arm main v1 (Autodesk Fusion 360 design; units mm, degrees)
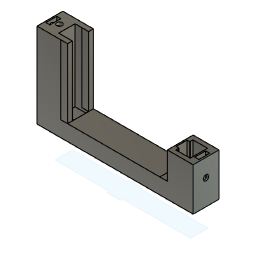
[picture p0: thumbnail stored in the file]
sketch "草图1" plane through (0, 0, 0) normal (0, 0, 1) x axis (1, 0, 0)
  line L1 (57.5, 9.5) -> (-57.5, 9.5)
  line L2 (57.5, -9.5) -> (57.5, 9.5)
  line L3 (-57.5, -9.5) -> (57.5, -9.5)
  line L4 (-57.5, 9.5) -> (-57.5, -9.5)
  line L5 (57.5, -9.5) -> (-57.5, 9.5)
  line L6 (-57.5, -9.5) -> (57.5, 9.5)
  point P6 (0, 0)
  point P1 (0, 0)
  point P4 (57.5, -9.5)
  point P5 (-57.5, -9.5)
  horizontal L1
  perpendicular L1 L2
  parallel L1 L3
  parallel L2 L4
  coincident L5 P6
  coincident L6 P6
  coincident P1 P6
  dimension "d1" distance P4 P5 = 115
  dimension "d2" distance L1 L3 = 19
extrude "拉伸1" new body sketch "草图1" profile of L1 L2 L3 L4 along normal blind 10
sketch "草图2" plane through (0, 0, 10) normal (0, 0, 1) x axis (-1, 0, 0)
  line L1 (-57.5, 9.5) -> (57.5, 9.5)
  line L2 (-57.5, -9.5) -> (-57.5, 9.5)
  line L3 (57.5, -9.5) -> (-57.5, -9.5)
  line L4 (57.5, 9.5) -> (57.5, -9.5)
  line L5 (-38.5, 9.5) -> (-57.5, 9.5)
  line L6 (-38.5, -9.5) -> (-38.5, 9.5)
  line L7 (-57.5, -9.5) -> (-38.5, -9.5)
  line L8 (-57.5, 9.5) -> (-57.5, -9.5)
  point P3 (-57.5, 9.5)
  point P6 (-57.5, 9.5)
  point P7 (-38.5, 9.5)
  horizontal L5
  vertical L6
  horizontal L7
  vertical L8
  coincident P3 P6
  dimension "d5" distance P6 P7 = 19
extrude "拉伸2" add sketch "草图2" profile of L1 L2 L3 L5 L6 L7 L8 along normal blind 20
sketch "草图3" plane through (0, 0, 30) normal (0, 0, 1) x axis (-1, 0, 0)
  line L1 (-38.5, -9.5) -> (-57.5, -9.5)
  line L2 (-38.5, 9.5) -> (-38.5, -9.5)
  line L3 (-57.5, 9.5) -> (-38.5, 9.5)
  line L4 (-57.5, -9.5) -> (-57.5, 9.5)
  line L5 (-41.5, 6.353) -> (-52.2, 6.353)
  line L6 (-52.2, -6.347) -> (-41.5, -6.347)
  line L7 (-41.5, -6.347) -> (-52.2, 6.353)
  line L8 (-52.2, -6.347) -> (-41.5, 6.353)
  line L9 (-52.2, -5.5) -> (-52.2, -6.347)
  line L10 (-52.2, 6.353) -> (-52.2, 5.5)
  line L11 (-52.2, -5.5) -> (-52.2, 5.5)
  line L12 (-41.5, 4.5005) -> (-41.5, 6.353)
  line L13 (-41.5, -6.347) -> (-41.5, -4.4995)
  line L14 (-39.5, 3.9901) -> (-41.5, 3.9901)
  line L15 (-39.5, -4.0099) -> (-39.5, 3.9901)
  line L16 (-41.5, -4.0099) -> (-39.5, -4.0099)
  line L17 (-39.5, -4.0099) -> (-41.5, 3.9901)
  line L18 (-41.5, -4.0099) -> (-39.5, 3.9901)
  line L19 (-56.2, 4) -> (-53.2, 4)
  line L20 (-56.2, -4) -> (-56.2, 4)
  line L21 (-53.2, -4) -> (-56.2, -4)
  line L22 (-53.2, 4) -> (-53.2, -4)
  line L23 (-56.2, -4) -> (-53.2, 4)
  line L24 (-53.2, -4) -> (-56.2, 4)
  line L25 (-41.5, 3.9901) -> (-41.5, 4.5005)
  line L26 (-41.5, -4.4995) -> (-41.5, -4.0099)
  point P10 (-46.85, 0.003)
  point P11 (-52.2, 5.5)
  point P20 (-40.5, -0.0099)
  point P15 (-40.5, -0.0099)
  point P25 (-54.7, 0)
  point P26 (-41.5, 3.9901)
  point P18 (-39.5, -4.0099)
  point P19 (-41.5, -4.0099)
  horizontal L5
  perpendicular L5 L12
  parallel L5 L6
  parallel L9 L12
  coincident L7 P10
  coincident L8 P10
  coincident P11 L9
  collinear L9 L10
  collinear L12 L13
  parallel L13 L25
  horizontal L14
  perpendicular L14 L15
  parallel L14 L16
  coincident L17 P20
  coincident L18 P20
  coincident P15 P20
  horizontal L19
  perpendicular L19 L20
  parallel L19 L21
  parallel L20 L22
  coincident L23 P25
  coincident L24 P25
  collinear L25 L26
  coincident L17 P26
  dimension "d24" distance L9 L12 = 10.7
  dimension "d25" distance L5 L6 = 12.7
  dimension "d26" distance L2 L12 = 3
  dimension "d32" distance P18 P19 = 2
  dimension "d33" distance L14 L16 = 8
  dimension "d34" distance P15 L25 = 1
  dimension "d35" distance L19 L21 = 8
  dimension "d36" distance L20 L22 = 3
  dimension "d37" distance L11 L22 = 1
sketch "草图4" plane through (38.5, 0, 0) normal (-1, 0, 0) x axis (0, -1, 0)
  line L1 (9.5, 10) -> (-9.5, 10)
  line L2 (9.5, 30) -> (9.5, 10)
  line L3 (-9.5, 30) -> (9.5, 30)
  line L4 (-9.5, 10) -> (-9.5, 30)
  circle C1 centre (0, 17) radius 2
  point P6 (0, 17)
  dimension "d20" diameter C1 = 4
  dimension "d21" distance L3 P6 = 13
extrude "拉伸6" cut sketch "草图3" profile of L5 L13 L6 L10 L11 L26 L14 L15 L16 against normal blind 47
extrude "拉伸7" cut sketch "草图3" profile of L19 L20 L21 L22 against normal blind 17
sketch "草图5" plane through (57.5, 0, 0) normal (1, 0, 0) x axis (0, 1, 0)
  line L1 (9.5, 0) -> (-9.5, 0)
  line L2 (9.5, 30) -> (9.5, 0)
  line L3 (-9.5, 30) -> (9.5, 30)
  line L4 (-9.5, 0) -> (-9.5, 30)
  circle C1 centre (0, 22) radius 2
  point P6 (0, 22)
  dimension "d42" diameter C1 = 4
  dimension "d43" distance L3 P6 = 8
extrude "拉伸8" cut sketch "草图5" profile of C1 against normal blind 13
sketch "草图6" plane through (0, 0, 10) normal (0, 0, 1) x axis (-1, 0, 0)
  line L1 (-38.5, -9.5) -> (-38.5, 9.5)
  line L2 (57.5, -9.5) -> (-38.5, -9.5)
  line L3 (57.5, 9.5) -> (57.5, -9.5)
  line L4 (-38.5, 9.5) -> (57.5, 9.5)
  line L5 (56.5, -4) -> (53.5, -4)
  line L6 (56.5, 4) -> (56.5, -4)
  line L7 (53.5, 4) -> (56.5, 4)
  line L8 (53.5, -4) -> (53.5, 4)
  line L9 (56.5, 4) -> (53.5, -4)
  line L10 (53.5, 4) -> (56.5, -4)
  circle C1 centre (50.5, 0) radius 2
  point P10 (55, 0)
  point P8 (56.5, 4)
  point P9 (53.5, 4)
  point P11 (50.5, 0)
  horizontal L5
  perpendicular L5 L6
  parallel L5 L7
  parallel L6 L8
  coincident L9 P10
  coincident L10 P10
  dimension "d48" distance P8 P9 = 3
  dimension "d49" distance L5 L7 = 8
  dimension "d131" diameter C1 = 4
  dimension "d132" distance L8 P11 = 3
extrude "拉伸10" cut sketch "草图6" profile of L5 L6 L7 L8 against normal blind 8
sketch "草图7" plane through (-57.5, 0, 0) normal (-1, 0, 0) x axis (0, -1, 0)
  line L1 (9.5, 0) -> (-9.5, 0)
  line L2 (9.5, 10) -> (9.5, 0)
  line L3 (-9.5, 10) -> (9.5, 10)
  line L4 (-9.5, 0) -> (-9.5, 10)
  circle C1 centre (0, 6) radius 2
  point P6 (0, 6)
  dimension "d56" diameter C1 = 4
  dimension "d57" distance L3 P6 = 4
sketch "草图9" plane through (0, 0, 0) normal (0, 0, -1) x axis (1, 0, 0)
  line L1 (-57.5, 9.5) -> (57.5, 9.5)
  line L2 (-57.5, -9.5) -> (-57.5, 9.5)
  line L3 (57.5, -9.5) -> (-57.5, -9.5)
  line L4 (57.5, 9.5) -> (57.5, -9.5)
  line L5 (-47.5, 6.3532) -> (52.5, 6.3532)
  line L6 (-47.5, -6.6468) -> (-47.5, 6.3532)
  line L7 (52.5, -6.6468) -> (-47.5, -6.6468)
  line L8 (52.5, 6.3532) -> (52.5, -6.6468)
  line L9 (41.5, -6.347) -> (52.2, -6.347)
  line L10 (41.5, -4.4995) -> (41.5, -6.347)
  line L11 (41.5, -4.0099) -> (41.5, -4.4995)
  line L12 (39.5, -4.0099) -> (41.5, -4.0099)
  line L13 (39.5, 3.9901) -> (39.5, -4.0099)
  line L14 (41.5, 3.9901) -> (39.5, 3.9901)
  line L15 (41.5, 4.5005) -> (41.5, 3.9901)
  line L16 (41.5, 6.353) -> (41.5, 4.5005)
  line L17 (52.2, 6.353) -> (41.5, 6.353)
  line L18 (52.2, -6.347) -> (52.2, 6.353)
  horizontal L5
  vertical L6
  horizontal L7
  vertical L8
  dimension "d70" distance L6 L8 = 100
  dimension "d71" distance L5 L7 = 13
extrude "拉伸12" cut sketch "草图9" profile of L5 L6 L7 against normal blind 3
sketch "草图10" plane through (0, 0, 3) normal (0, 0, -1) x axis (1, 0, 0)
  line L1 (41.5, -6.347) -> (52.2, -6.347)
  line L2 (52.2, 6.353) -> (41.5, 6.353)
  line L3 (-47.5, -6.6468) -> (-47.5, 6.3532)
  line L4 (56.2, -6.347) -> (52.2, -6.347)
  line L5 (56.2, 6.353) -> (56.2, -6.347)
  line L6 (52.2, 6.353) -> (56.2, 6.353)
  line L7 (52.2, -6.347) -> (52.2, 6.353)
  line L8 (52.5, 6.3532) -> (52.5, -6.6468)
  line L9 (41.5, 3.9901) -> (39.5, 3.9901)
  line L10 (41.5, 4.5005) -> (41.5, 3.9901)
  line L11 (41.5, 6.353) -> (41.5, 4.5005)
  line L12 (52.2, -6.347) -> (52.2, 6.353)
  line L13 (41.5, -4.4995) -> (41.5, -6.347)
  line L14 (41.5, -4.0099) -> (41.5, -4.4995)
  line L15 (39.5, -4.0099) -> (41.5, -4.0099)
  line L16 (39.5, 3.9901) -> (39.5, -4.0099)
  line L17 (-47.5, 6.3532) -> (52.5, 6.3532)
  line L18 (52.5, -6.6468) -> (-47.5, -6.6468)
  point P8 (56.2, 6.353)
  point P2 (52.2, -6.347)
  point P6 (52.2, -6.347)
  horizontal L4
  vertical L5
  horizontal L6
  vertical L7
  coincident L2 P8
  coincident P2 P6
  dimension "d65" distance L5 L7 = 4
extrude "拉伸14" cut sketch "草图10" profile of L1 L2 L3 L4 L5 L6 L7 against normal blind 19
sketch "草图12" plane through (0, 0, 0) normal (0, 0, -1) x axis (1, 0, 0)
  line L1 (-57.5, 9.5) -> (57.5, 9.5)
  line L2 (-57.5, -9.5) -> (-57.5, 9.5)
  line L3 (57.5, -9.5) -> (-57.5, -9.5)
  line L4 (57.5, 9.5) -> (57.5, -9.5)
  line L5 (-47.5, -6.6468) -> (52.5, -6.6468)
  line L6 (-47.5, 6.3532) -> (-47.5, -6.6468)
  line L7 (52.5, 6.3532) -> (-47.5, 6.3532)
  line L8 (2.5, -8) -> (-7.5, -8)
  line L9 (2.5, 8) -> (2.5, -8)
  line L10 (-7.5, 8) -> (2.5, 8)
  line L11 (-7.5, -8) -> (-7.5, 8)
  line L12 (52.5, -6.6468) -> (52.5, 6.3532)
  horizontal L8
  vertical L9
  horizontal L10
  vertical L11
  dimension "d68" distance L9 L11 = 10
  dimension "d69" distance L8 L10 = 16
  dimension "d72" distance L6 L11 = 40
extrude "拉伸17" add of existing geometry blind 1.5
sketch "草图14" plane through (0, 0, -1.5) normal (0, 0, -1) x axis (1, 0, 0)
  line L1 (-57.5, 9.5) -> (57.5, 9.5)
  line L2 (-57.5, -9.5) -> (-57.5, 9.5)
  line L3 (57.5, -9.5) -> (-57.5, -9.5)
  line L4 (57.5, 9.5) -> (57.5, -9.5)
  line L5 (-47.5, -6.6468) -> (52.5, -6.6468)
  line L6 (-47.5, 6.3532) -> (-47.5, -6.6468)
  line L7 (52.5, 6.3532) -> (-47.5, 6.3532)
  line L8 (52.5, -6.6468) -> (52.5, 6.3532)
  circle C1 centre (-51.5, 0) radius 1.5
extrude "拉伸18" add sketch "草图14" profile of C1 against normal blind 1
sketch "草图15" plane through (0, 0, -1.5) normal (0, 0, -1) x axis (1, 0, 0)
  line L1 (-57.5, 9.5) -> (57.5, 9.5)
  line L2 (-57.5, -9.5) -> (-57.5, 9.5)
  line L3 (57.5, -9.5) -> (-57.5, -9.5)
  line L4 (57.5, 9.5) -> (57.5, -9.5)
  line L5 (-47.5, -6.6468) -> (52.5, -6.6468)
  line L6 (-47.5, 6.3532) -> (-47.5, -6.6468)
  line L7 (52.5, 6.3532) -> (-47.5, 6.3532)
  line L8 (2.5, -8) -> (-7.5, -8)
  line L9 (2.5, -6.6468) -> (2.5, -8)
  line L10 (-7.5, -6.6468) -> (2.5, -6.6468)
  line L11 (-7.5, -8) -> (-7.5, -6.6468)
  line L12 (-7.5, 6.3532) -> (2.5, 6.3532)
  line L13 (-7.5, 8) -> (-7.5, 6.3532)
  line L14 (2.5, 8) -> (-7.5, 8)
  line L15 (2.5, 6.3532) -> (2.5, 8)
  line L16 (52.5, -6.6468) -> (52.5, 6.3532)
  point P12 (2.5, -6.6468)
  point P14 (2.5, 6.3532)
  horizontal L8
  vertical L9
  horizontal L10
  vertical L11
  midpoint L5 P12
  horizontal L12
  vertical L13
  horizontal L14
  vertical L15
  midpoint L7 P14
extrude "拉伸19" cut sketch "草图15" profile of L5 L7 L8 L9 L10 L11 L12 L13 L14 L15 against normal blind 1
sketch "草图16" plane through (0, 0, -21) normal (0, 0, -1) x axis (1, 0, 0)
  line L1 (-7.5, 8) -> (2.5, 8)
  line L2 (-7.5, 6.3532) -> (-7.5, 8)
  line L3 (-47.5, 6.3532) -> (-7.5, 6.3532)
  line L4 (-47.5, -6.6468) -> (-47.5, 6.3532)
  line L5 (-7.5, -6.6468) -> (-47.5, -6.6468)
  line L6 (-7.5, -8) -> (-7.5, -6.6468)
  line L7 (2.5, -8) -> (-7.5, -8)
  line L8 (2.5, -6.6468) -> (2.5, -8)
  line L9 (52.5, -6.6468) -> (2.5, -6.6468)
  line L10 (52.5, 6.3532) -> (52.5, -6.6468)
  line L11 (2.5, 6.3532) -> (52.5, 6.3532)
  line L12 (2.5, 8) -> (2.5, 6.3532)
sketch "草图17" plane through (0, 0, 10) normal (0, 0, 1) x axis (-1, 0, 0)
  line L1 (53.5, -4) -> (56.5, -4)
  line L2 (53.5, 4) -> (53.5, -4)
  line L3 (56.5, 4) -> (53.5, 4)
  line L4 (56.5, -4) -> (56.5, 4)
  line L5 (-38.5, -9.5) -> (-38.5, 9.5)
  line L6 (57.5, -9.5) -> (-38.5, -9.5)
  line L7 (57.5, 9.5) -> (57.5, -9.5)
  line L8 (-38.5, 9.5) -> (57.5, 9.5)
extrude "拉伸20" add sketch "草图17" along normal blind 11
sketch "草图19" plane through (0, 9.5, 0) normal (0, 1, 0) x axis (-1, 0, 0)
  line L1 (57.5, 10) -> (-38.5, 10)
  line L2 (57.5, 21) -> (57.5, 10)
  line L3 (-38.5, 21) -> (57.5, 21)
  line L4 (-33, 21) -> (40, 21)
  line L5 (40, 10) -> (-33, 10)
  line L6 (40, 21) -> (40, 10)
  line L7 (-33, 21) -> (-33, 10)
  line L8 (-38.5, 10) -> (-38.5, 21)
  point P6 (40, 21)
  horizontal L4
  horizontal L5
  vertical L6
  coincident L3 P6
extrude "拉伸22" cut sketch "草图19" profile of L1 L3 L4 L5 L6 L7 against normal blind 30
extrude "拉伸25" cut sketch "草图6" profile of C1 along normal blind 16
sketch "草图22" plane through (0, -9.5, 0) normal (0, -1, 0) x axis (1, 0, 0)
  line L1 (33, 10) -> (33, 21)
  line L2 (-40, 10) -> (33, 10)
  line L3 (-40, 21) -> (-40, 10)
  line L4 (-57.5, 21) -> (-40, 21)
  line L5 (-57.5, -1.5) -> (-57.5, 21)
  line L6 (57.5, -1.5) -> (-57.5, -1.5)
  line L7 (57.5, 30) -> (57.5, -1.5)
  line L8 (38.5, 30) -> (57.5, 30)
  line L9 (38.5, 21) -> (38.5, 30)
  line L10 (33, 21) -> (38.5, 21)
  line L11 (38.5, 10) -> (33, 10)
  line L12 (38.5, 21) -> (38.5, 10)
  line L13 (33, 21) -> (38.5, 21)
  line L14 (33, 10) -> (33, 21)
  point P11 (38.5, 21)
  point P14 (38.5, 21)
  point P3 (33, 10)
  point P12 (33, 10)
  horizontal L11
  vertical L12
  horizontal L13
  vertical L14
  coincident P11 P14
  coincident P3 P12
extrude "拉伸26" cut sketch "草图22" profile of L1 L10 L11 L12 L13 L14 against normal blind 70
sketch "草图23" plane through (0, 0, 30) normal (0, 0, 1) x axis (-1, 0, 0)
  line L1 (-53.2, 4) -> (-56.2, 4)
  line L2 (-53.2, -4) -> (-53.2, 4)
  line L3 (-56.2, -4) -> (-53.2, -4)
  line L4 (-56.2, 4) -> (-56.2, -4)
  line L5 (-52.2, -6.347) -> (-41.5, -6.347)
  line L6 (-52.2, 6.353) -> (-52.2, -6.347)
  line L7 (-41.5, 6.353) -> (-52.2, 6.353)
  line L8 (-41.5, 4.5005) -> (-41.5, 6.353)
  line L9 (-41.5, 3.9901) -> (-41.5, 4.5005)
  line L10 (-39.5, 3.9901) -> (-41.5, 3.9901)
  line L11 (-39.5, -4.0099) -> (-39.5, 3.9901)
  line L12 (-41.5, -4.0099) -> (-39.5, -4.0099)
  line L13 (-41.5, -4.4995) -> (-41.5, -4.0099)
  line L14 (-41.5, -6.347) -> (-41.5, -4.4995)
  line L15 (-38.5, -9.5) -> (-57.5, -9.5)
  line L16 (-38.5, 9.5) -> (-38.5, -9.5)
  line L17 (-57.5, 9.5) -> (-38.5, 9.5)
  line L18 (-57.5, -9.5) -> (-57.5, 9.5)
extrude "拉伸27" add sketch "草图23" against normal blind 27
sketch "草图24" plane through (57.5, 0, 0) normal (1, 0, 0) x axis (0, 1, 0)
  line L1 (-9.5, -1.5) -> (-9.5, 30)
  line L2 (9.5, -1.5) -> (-9.5, -1.5)
  line L3 (9.5, 30) -> (9.5, -1.5)
  line L4 (-9.5, 30) -> (9.5, 30)
sketch "草图25" plane through (57.5, 0, 0) normal (1, 0, 0) x axis (0, 1, 0)
  line L1 (-9.5, 30) -> (9.5, 30)
  circle C1 centre (0, 17) radius 2
  point P2 (0, 17)
  dimension "d139" diameter C1 = 4
  dimension "d140" distance P2 L1 = 13
extrude "拉伸28" cut sketch "草图25" profile of C1 against normal blind 11
extrude "拉伸29" cut of existing geometry blind -5
sketch "草图26" plane through (0, 0, 10) normal (0, 0, 1) x axis (-1, 0, 0)
  line L1 (-33, 9.5) -> (40, 9.5)
  line L2 (-33, -9.5) -> (-33, 9.5)
  line L3 (40, -9.5) -> (-33, -9.5)
  line L4 (40, 9.5) -> (40, -9.5)
  line L5 (45, -6) -> (35, -6)
  line L6 (45, 6) -> (45, -6)
  line L7 (35, 6) -> (45, 6)
  line L8 (35, -6) -> (35, 6)
  line L9 (45, 6) -> (35, -6)
  line L10 (35, 6) -> (45, -6)
  point P10 (40, 0)
  horizontal L5
  perpendicular L5 L6
  parallel L5 L7
  parallel L6 L8
  coincident L9 P10
  coincident L10 P10
  midpoint L4 P10
extrude "拉伸30" cut sketch "草图26" profile of L4 L5 L7 L8 against normal blind 27
sketch "草图27" plane through (0, 0, 8) normal (0, 0, -1) x axis (1, 0, 0)
  line L1 (-40, -6) -> (-35, -6)
  line L2 (-40, 6) -> (-40, -6)
  line L3 (-35, 6) -> (-40, 6)
  line L4 (-35, -6) -> (-35, 6)
  line L5 (52.5, 6.3532) -> (52.5, -6.6468)
  line L6 (-47.5, 6.3532) -> (52.5, 6.3532)
  line L7 (-47.5, -6.6468) -> (-47.5, 6.3532)
  line L8 (52.5, -6.6468) -> (-47.5, -6.6468)
  line L9 (52.2, -6.347) -> (52.2, 6.353)
  line L10 (41.5, -6.347) -> (52.2, -6.347)
  line L11 (41.5, -4.4995) -> (41.5, -6.347)
  line L12 (41.5, -4.0099) -> (41.5, -4.4995)
  line L13 (39.5, -4.0099) -> (41.5, -4.0099)
  line L14 (39.5, 3.9901) -> (39.5, -4.0099)
  line L15 (41.5, 3.9901) -> (39.5, 3.9901)
  line L16 (41.5, 4.5005) -> (41.5, 3.9901)
  line L17 (41.5, 6.353) -> (41.5, 4.5005)
  line L18 (52.2, 6.353) -> (41.5, 6.353)
  line L19 (-45, 6) -> (-40, 6)
  line L20 (-45, -6) -> (-45, 6)
  line L21 (-40, -6) -> (-45, -6)
  line L22 (-40, -6) -> (-40, 6)
  point P4 (-40, 6)
  point P22 (-40, 6)
  point P3 (-40, -6)
  point P23 (-40, -6)
  horizontal L19
  vertical L20
  horizontal L21
  coincident P4 P22
  coincident P3 P23
extrude "拉伸31" cut sketch "草图27" profile of L2 L19 L20 L21 L22 against normal blind 34
extrude "拉伸32" cut of existing geometry blind -1
extrude "拉伸33" cut of existing geometry blind -1
extrude "拉伸34" add of existing geometry blind 40
extrude "拉伸35" add of existing geometry blind 5
sketch "草图28" plane through (-57.5, 0, 0) normal (-1, 0, 0) x axis (0, -1, 0)
  line L1 (9.5, 61) -> (9.5, -1.5)
  line L2 (-9.5, 61) -> (9.5, 61)
  line L3 (-9.5, 10) -> (-9.5, 61)
  line L4 (-9.5, -1.5) -> (-9.5, 10)
  line L5 (9.5, -1.5) -> (-9.5, -1.5)
  circle C1 centre (0, 57) radius 2
  point P7 (0, 57)
  dimension "d158" diameter C1 = 4
  dimension "d159" distance L2 P7 = 4
extrude "拉伸36" cut sketch "草图28" profile of C1 against normal blind 7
